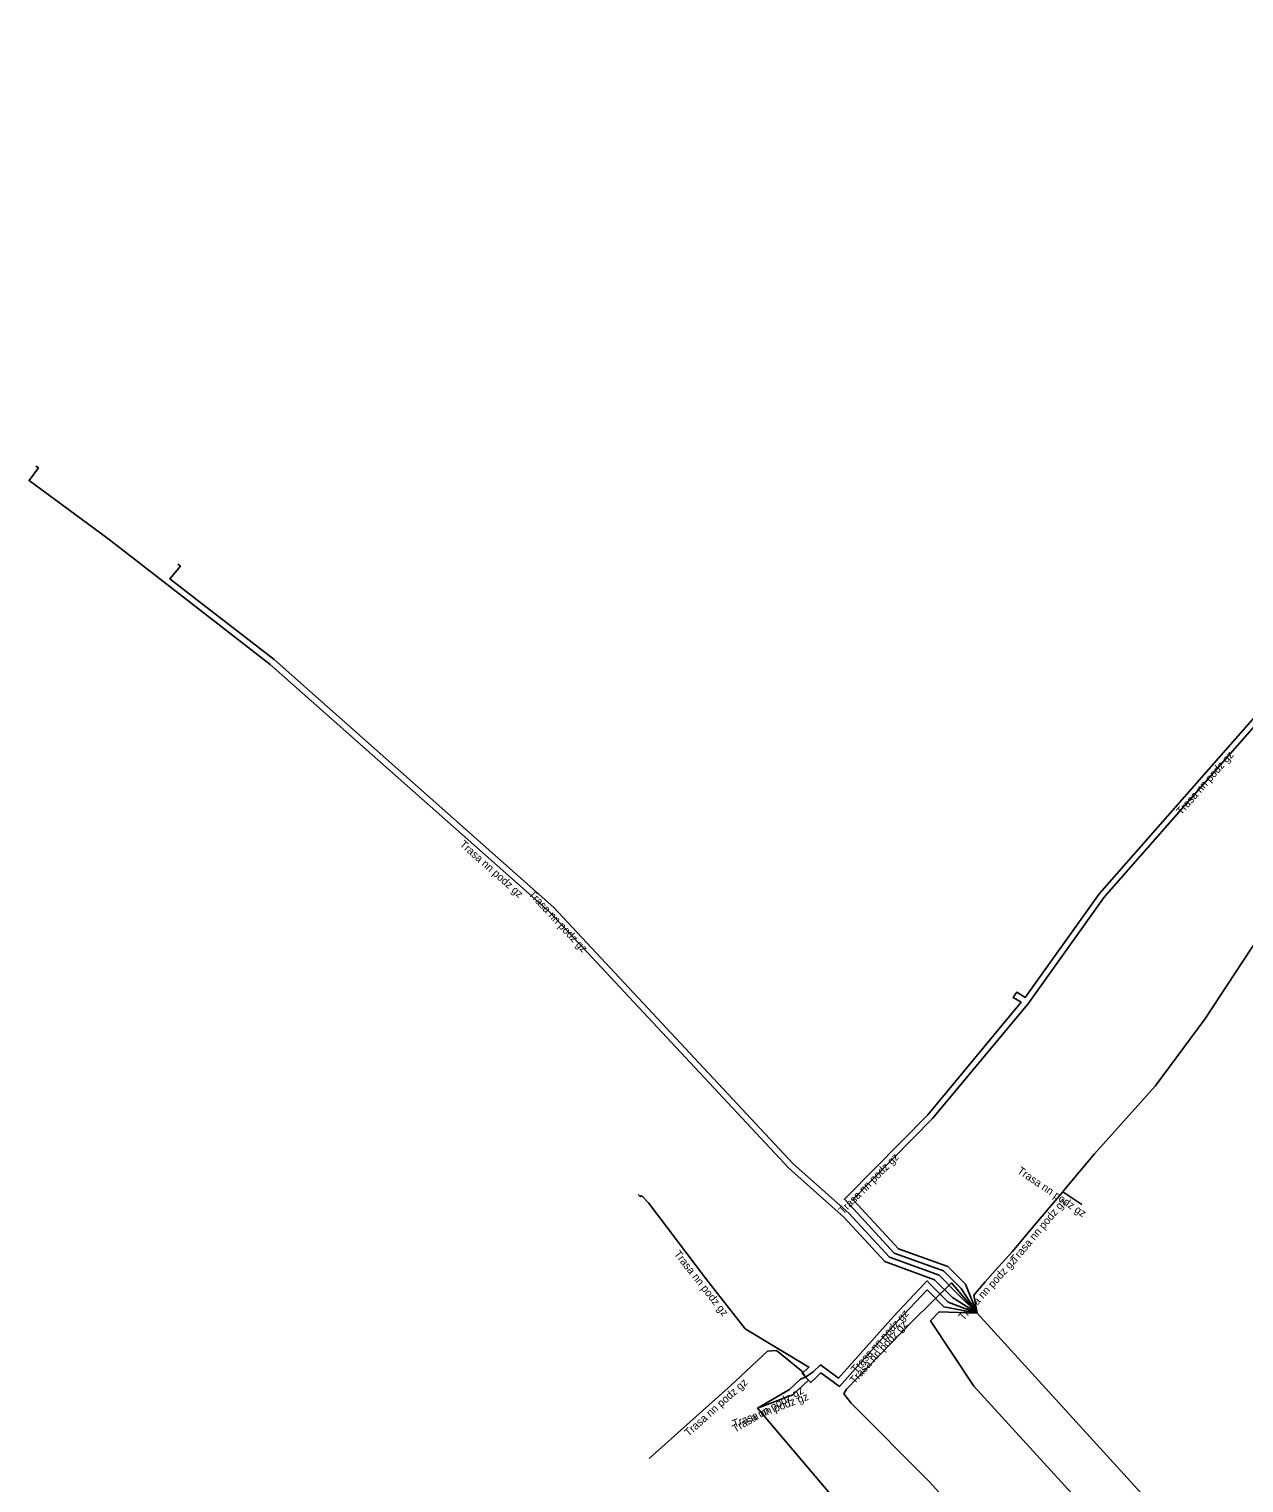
# Model space of a CAD drawing. Extents: x -724448 to -724084, y -973287 to -972828.
# Drawn here: x -724447.6 to -724369.4, y -973081 to -972987.4 of the extents above; entities that cross this region are included whole.
import ezdxf

# ---------------------------------------------------------------- set-up
doc = ezdxf.new("R2010")
doc.units = 0
for name, color, linetype in [('Popiskový text - Ostatní atributy Trasy', 7, 'Continuous'), ('Spojnice NN', 7, 'Continuous'), ('Spojnice VN', 7, 'Continuous')]:
    doc.layers.add(name, color=color, linetype=linetype)

msp = doc.modelspace()

# ---------------------------------------------------------------- linework, layer by layer
at = {"layer": 'Spojnice NN'}
for points in [[(-724386.52, -973070.11), (-724387.286, -973068.226), (-724388.422, -973067.097), (-724391.589, -973065.963), (-724394.209, -973063.123), (-724394.527, -973062.778), (-724389.405, -973057.578), (-724383.26, -973050.202), (-724378.343, -973043.324), (-724368.042, -973031.604), (-724357.647, -973020.499), (-724343.86, -973002.323), (-724335.869, -972994.552), (-724327.848, -972986.481), (-724319.028, -972977.579), (-724319.731, -972976.876)], [(-724386.52, -973070.11), (-724388.116, -973069.1), (-724389.269, -973067.948), (-724392.471, -973066.777), (-724395.091, -973063.937), (-724398.666, -973060.757), (-724414.07, -973044.263), (-724432.058, -973028.334), (-724437.043, -973024.458), (-724442.497, -973020.232), (-724447.573, -973016.492), (-724446.977, -973015.678), (-724447.138, -973015.56)], [(-724359.22, -973019.93), (-724359.356, -973020.077), (-724358.521, -973020.848), (-724368.338, -973031.336), (-724378.657, -973043.076), (-724383.445, -973049.773), (-724383.981, -973049.445), (-724384.1, -973049.61)], [(-724349.11, -973020.38), (-724349.63, -973020.43), (-724356.73, -973029.95), (-724361.12, -973035.46), (-724361.27, -973037.29), (-724363.95, -973039.64), (-724367.03, -973043.78), (-724371.88, -973051.18), (-724375.06, -973055.48), (-724378.98, -973059.85), (-724380.891, -973062.126), (-724381.02, -973062.28)], [(-724386.52, -973070.11), (-724387.839, -973068.81), (-724388.987, -973067.664), (-724392.177, -973066.506), (-724394.797, -973063.666), (-724398.374, -973060.483), (-724413.79, -973043.977), (-724431.802, -973028.026), (-724436.797, -973024.142), (-724438.504, -973022.82), (-724437.831, -973022.002), (-724437.986, -973021.875)], [(-724386.52, -973070.11), (-724387.564, -973068.519), (-724388.705, -973067.381), (-724391.883, -973066.234), (-724394.503, -973063.394), (-724395.08, -973062.769), (-724394.902, -973062.59), (-724389.715, -973057.322), (-724383.695, -973050.089), (-724384.215, -973049.774), (-724384.1, -973049.61)], [(-724408.36, -973062.47), (-724408.215, -973062.608), (-724408.138, -973062.527), (-724407.69, -973063), (-724404.03, -973067.85), (-724401.46, -973071.11), (-724397.358, -973073.579), (-724397.794, -973073.989), (-724397.589, -973074.231)], [(-724381.02, -973062.28), (-724381.149, -973062.434), (-724383.07, -973064.72)], [(-724381.02, -973062.28), (-724379.8, -973063.11)], [(-724383.069, -973064.72), (-724384.27, -973066.15), (-724385.34, -973067.34), (-724386.01, -973068.09), (-724386.74, -973068.94), (-724386.52, -973070.11)], [(-724397.589, -973074.231), (-724397.084, -973073.87), (-724396.619, -973073.433), (-724395.458, -973074.281), (-724391.917, -973070.315), (-724389.895, -973068.18), (-724389.753, -973068.03), (-724389.551, -973068.231), (-724388.387, -973069.384), (-724386.52, -973070.11)], [(-724386.52, -973070.11), (-724388.18, -973068.15), (-724390.69, -973070.61), (-724394.94, -973075), (-724395.11, -973075.29), (-724394.64, -973075.9), (-724389.6, -973080.97), (-724384.24, -973086.91), (-724377.78, -973093.87), (-724372.74, -973099.48), (-724366.69, -973106.05), (-724359.48, -973114.27), (-724356.72, -973117.52), (-724349.06, -973126.39), (-724343.05, -973133.21), (-724333.65, -973144.14)], [(-724397.589, -973074.231), (-724397.246, -973074.571), (-724396.81, -973074.161), (-724396.587, -973073.952), (-724395.402, -973074.819), (-724391.623, -973070.585), (-724389.745, -973068.603), (-724388.674, -973069.685), (-724386.52, -973070.11)], [(-724386.52, -973070.11), (-724388.987, -973070.015), (-724389.54, -973070.59), (-724386.74, -973074.8), (-724376.37, -973086.16), (-724367.04, -973095.69), (-724355.67, -973108.25)], [(-724397.589, -973074.231), (-724397.85, -973073.82), (-724399.46, -973072.51), (-724400.02, -973072.54), (-724402.37, -973074.74), (-724407.65, -973079.47)], [(-724397.589, -973074.231), (-724397.895, -973074.355), (-724398.618, -973075.026), (-724400.68, -973076.22)], [(-724400.68, -973076.22), (-724398.392, -973075.362), (-724397.384, -973074.427), (-724397.589, -973074.231)], [(-724369.62, -973112.83), (-724400.68, -973076.22)]]:
    msp.add_lwpolyline(points, dxfattribs=at)
at = {"layer": 'Spojnice VN'}
msp.add_lwpolyline([(-724358.638, -973100.722), (-724386.52, -973070.11)], dxfattribs=at)

# ---------------------------------------------------------------- texts
at = {"layer": 'Popiskový text - Ostatní atributy Trasy'}
for rotation, p in [(48.6858, (-724373.389, -973038.067)), (318.47399, (-724419.89, -973039.977)), (313.04435, (-724415.455, -973043.146)), (45.44389, (-724395.153, -973063.771)), (325.77145, (-724383.995, -973061.043)), (49.95857, (-724384.053, -973066.899)), (308.25025, (-724406.08, -973066.3)), (48.0394, (-724387.41, -973070.614)), (48.24027, (-724394.338, -973074.003)), (48.24992, (-724394.424, -973074.699)), (41.85504, (-724405.114, -973078.071)), (30.06995, (-724402.123, -973077.806)), (20.55399, (-724402.177, -973077.475))]:
    msp.add_text('Trasa nn podz gz', height=0.5, rotation=rotation, dxfattribs=at).set_placement(p)

doc.saveas('drawing.dxf')
